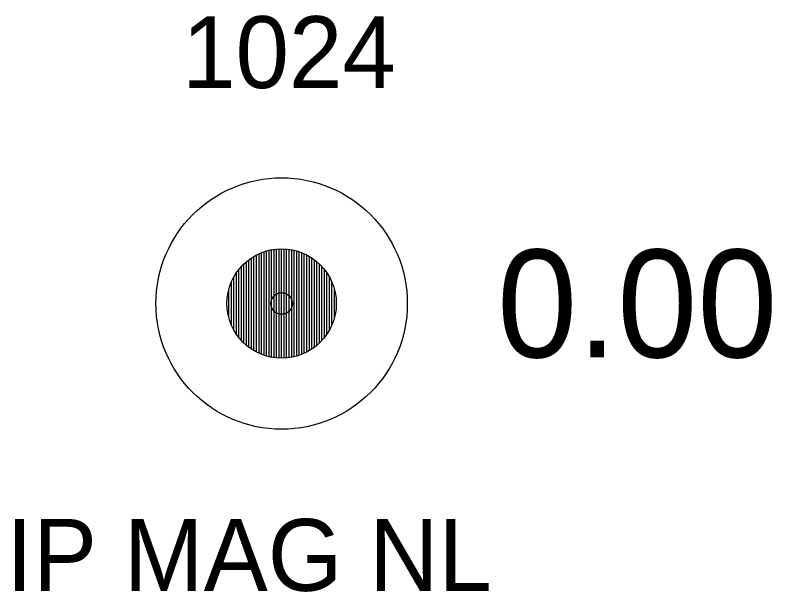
# Model space of a CAD drawing. Extents: x 1448136 to 1453623, y 1125056 to 1128842.
# Drawn here: x 1453303.4 to 1453313.93, y 1126045.7 to 1126053.73 of the extents above; entities that cross this region are included whole.
import ezdxf

# ---------------------------------------------------------------- set-up
doc = ezdxf.new("R2010")
doc.units = 0
for name, color, linetype in [('RD_EX_DV_Prop_txCode', 7, 'Continuous'), ('RD_EX_DV_PropPin', 7, 'Continuous'), ('RD_EX_TX_DV_Prop_ELEV', 7, 'Continuous'), ('RD_SMD_Locator', 7, 'Continuous')]:
    doc.layers.add(name, color=color, linetype=linetype)

msp = doc.modelspace()

# ---------------------------------------------------------------- linework, layer by layer
at = {"layer": 'RD_EX_DV_PropPin'}
for p, q in [((1453306.758, 1126049.037), (1453306.758, 1126050.389)), ((1453306.793, 1126049.02), (1453306.793, 1126050.406)), ((1453306.828, 1126049.005), (1453306.828, 1126050.421)), ((1453306.863, 1126048.993), (1453306.863, 1126050.433)), ((1453306.898, 1126048.982), (1453306.898, 1126050.444)), ((1453306.933, 1126048.972), (1453306.933, 1126050.454)), ((1453306.968, 1126048.965), (1453306.968, 1126050.461)), ((1453307.003, 1126048.959), (1453307.003, 1126050.467)), ((1453307.038, 1126048.955), (1453307.038, 1126050.471)), ((1453307.073, 1126048.953), (1453307.073, 1126050.473)), ((1453307.108, 1126048.952), (1453307.108, 1126050.474)), ((1453307.143, 1126048.953), (1453307.143, 1126050.473)), ((1453307.178, 1126048.955), (1453307.178, 1126050.471)), ((1453307.213, 1126048.959), (1453307.213, 1126050.467)), ((1453307.248, 1126048.965), (1453307.248, 1126050.461)), ((1453307.283, 1126048.972), (1453307.283, 1126050.454)), ((1453307.318, 1126048.982), (1453307.318, 1126050.444)), ((1453307.353, 1126048.993), (1453307.353, 1126050.433)), ((1453307.388, 1126049.005), (1453307.388, 1126050.421)), ((1453307.424, 1126049.02), (1453307.424, 1126050.406)), ((1453307.459, 1126049.037), (1453307.459, 1126050.389)), ((1453306.618, 1126049.131), (1453306.618, 1126050.295)), ((1453306.653, 1126049.103), (1453306.653, 1126050.323)), ((1453306.688, 1126049.078), (1453306.688, 1126050.348)), ((1453306.723, 1126049.057), (1453306.723, 1126050.369)), ((1453307.494, 1126049.057), (1453307.494, 1126050.369)), ((1453307.529, 1126049.078), (1453307.529, 1126050.348)), ((1453307.564, 1126049.103), (1453307.564, 1126050.323)), ((1453307.599, 1126049.131), (1453307.599, 1126050.295)), ((1453306.513, 1126049.239), (1453306.513, 1126050.187)), ((1453306.548, 1126049.198), (1453306.548, 1126050.228)), ((1453306.583, 1126049.162), (1453306.583, 1126050.264)), ((1453307.634, 1126049.162), (1453307.634, 1126050.264)), ((1453307.669, 1126049.198), (1453307.669, 1126050.228)), ((1453307.704, 1126049.239), (1453307.704, 1126050.187)), ((1453306.443, 1126049.343), (1453306.443, 1126050.083)), ((1453306.478, 1126049.286), (1453306.478, 1126050.14)), ((1453307.739, 1126049.286), (1453307.739, 1126050.14)), ((1453307.774, 1126049.343), (1453307.774, 1126050.083)), ((1453306.408, 1126049.415), (1453306.408, 1126050.011)), ((1453307.809, 1126049.415), (1453307.809, 1126050.011)), ((1453306.373, 1126049.517), (1453306.373, 1126049.909)), ((1453307.844, 1126049.517), (1453307.844, 1126049.909))]:
    msp.add_line(p, q, dxfattribs=at)
for radius in [1.75, 0.761]:
    msp.add_circle((1453307.108, 1126049.713), radius, dxfattribs=at)
at = {"layer": 'RD_SMD_Locator'}
msp.add_circle((1453307.108, 1126049.713), 0.15, dxfattribs=at)

# ---------------------------------------------------------------- texts
at = {"layer": 'RD_EX_DV_Prop_txCode'}
for s, p in [('1024', (1453305.723, 1126052.713)), ('IP MAG NL', (1453303.274, 1126045.713))]:
    msp.add_text(s, height=1, dxfattribs=at).set_placement(p)
at = {"layer": 'RD_EX_TX_DV_Prop_ELEV'}
msp.add_text('0.00', height=1.5, dxfattribs=at).set_placement((1453310.108, 1126048.963))

doc.saveas('drawing.dxf')
